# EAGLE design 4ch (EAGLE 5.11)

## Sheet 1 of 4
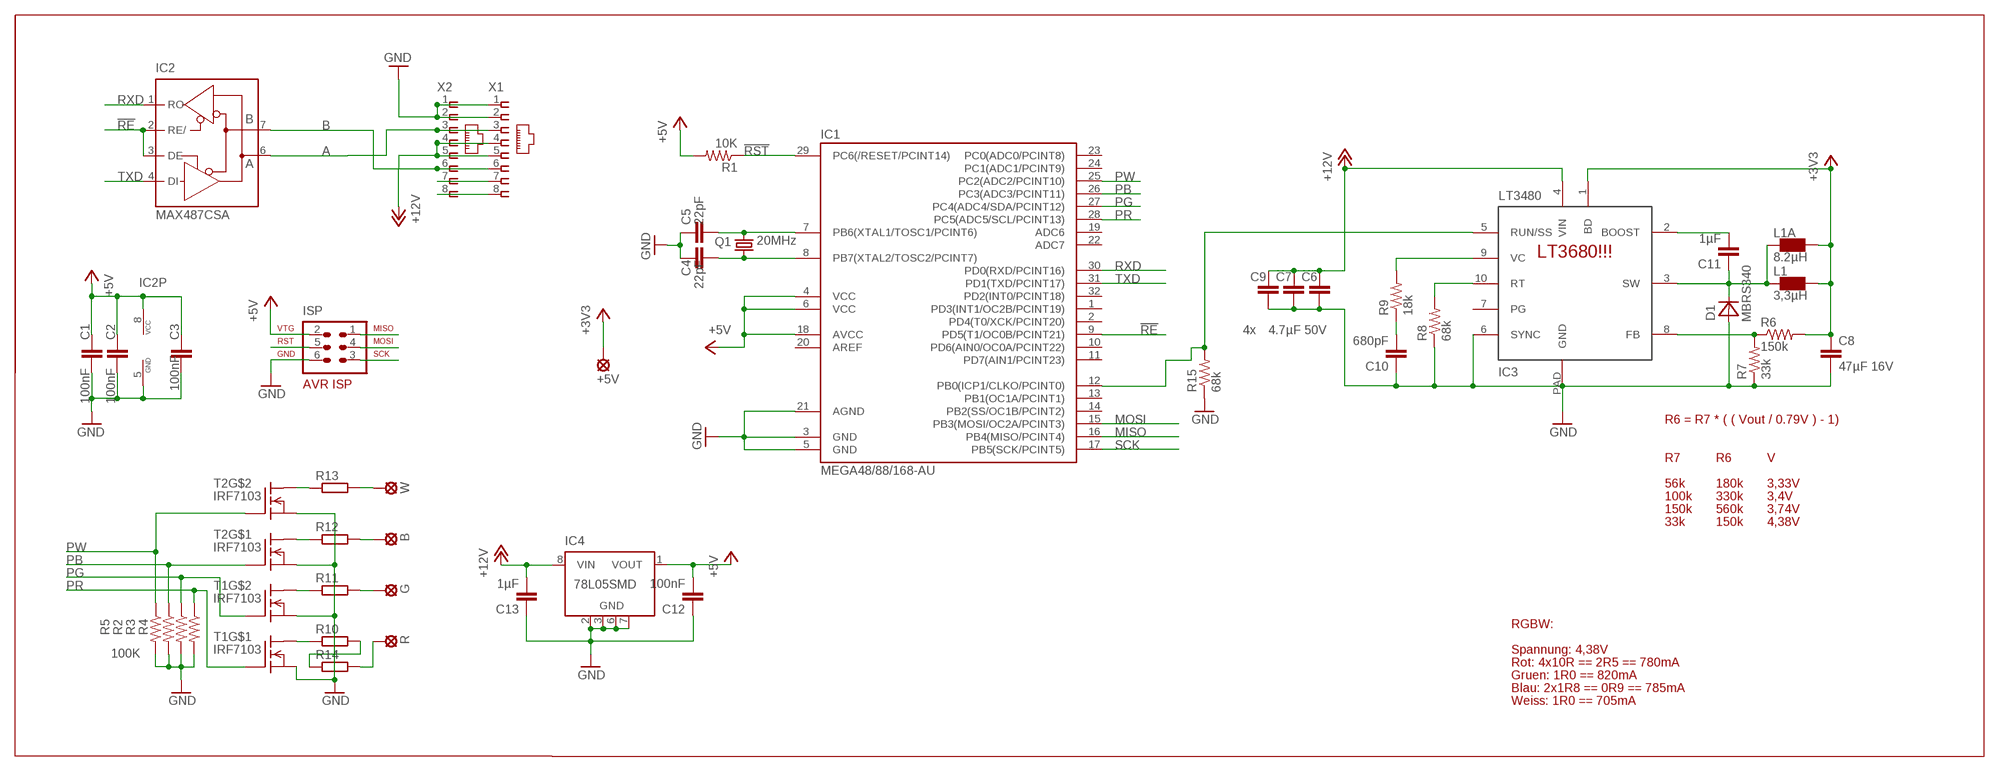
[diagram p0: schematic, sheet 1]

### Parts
+5V  SE14  [SE14]
B  SE14  [SE14]
C1  100nF  CAP0402-CAP  [0402-CAP]
C2  100nF  CAP0402-CAP  [0402-CAP]
C3  100nF  CAP0402-CAP  [0402-CAP]
C4  22pF  CAP0402-CAP  [0402-CAP]
C5  22pF  CAP0402-CAP  [0402-CAP]
C6  4.7µF 50V  CAP1210  [1210]
C7  4.7µF 50V  CAP1210  [1210]
C8  47µF 16V  CAP1210  [1210]
C9  4.7µF 50V  CAP1210  [1210]
C10  680pF  CAP0805  [0805]
C11  1µF  CAP0805  [0805]
C12  100nF  CAP0402-CAP  [0402-CAP]
C13  1µF  CAP0805  [0805]
D1  MBRS340  [DO214AB]
G  SE14  [SE14]
IC1  MEGA48/88/168-AU  [TQFP32-08]
IC2  MAX487CSA  MAX481CSA  [SO08]
IC3  LT3972  LT3480  [MSOP10-PAD]
IC4  78L05SMD  [SO08]
ISP  AVR-ISP-6  [AVR-ISP-6]
L1  3,3µH  TDK_RLF7030  [RLF7030]
L1A  8.2µH  IHLP-2525CZ  [IHLP-2525CZ]
Q1  20MHz  X22-OSCILLATOR  [X22]
R  SE14  [SE14]
R1  10K  RESISTOR0402-RES  [0402-RES]
R2  100K  RESISTOR0402-RES  [0402-RES]
R3  100K  RESISTOR0402-RES  [0402-RES]
R4  100K  RESISTOR0402-RES  [0402-RES]
R5  100K  RESISTOR0402-RES  [0402-RES]
R6  150k  RESISTOR0805-RES  [0805]
R7  33k  RESISTOR0805-RES  [0805]
R8  68k  RESISTOR0805-RES  [0805]
R9  18k  RESISTOR0805-RES  [0805]
R10  R-EU_MELF0207R  [MINI_MELF-0207R]
R11  R-EU_MELF0207R  [MINI_MELF-0207R]
R12  R-EU_MELF0207R  [MINI_MELF-0207R]
R13  R-EU_MELF0207R  [MINI_MELF-0207R]
R14  R-EU_MELF0207R  [MINI_MELF-0207R]
R15  68k  RESISTOR0402-RES  [0402-RES]
T1  IRF7103  [SO-8]
T2  IRF7103  [SO-8]
W  SE14  [SE14]
X1  RJ45-8L-B  [RJ45-NO-SHIELD]
X2  RJ45-8L-B  [RJ45-NO-SHIELD]

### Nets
!RE: IC1.9(PD5(T1/OC0B/PCINT21)) IC2.2(RE/) IC2.3(DE)
!RST: IC1.29(PC6(/RESET/PCINT14)) ISP.5 R1.1
+3V3: +5V.MP C8.1 IC3.1(BD) L1.P$1 L1A.P$1 R6.2
+5V: C1.1 C2.1 C3.1 C12.2 IC1.4(VCC) IC1.6(VCC) IC1.18(AVCC) IC2.8(VCC) IC4.1(VOUT) ISP.2 R1.2
+12V: C6.1 C7.1 C9.1 C13.2 IC3.4(VIN) IC4.8(VIN) X1.4 X1.5 X2.4 X2.5
A: IC2.6(A) X1.3 X2.3
B: IC2.7(B) X1.6 X2.6
GND: C1.2 C2.2 C3.2 C4.1 C5.1 C6.2 C7.2 C8.2 C9.2 C10.1 C12.1 C13.1 D1.A IC1.3(GND) IC1.5(GND) IC1.21(AGND) IC2.5(GND) IC3.6(SYNC) IC3.PAD(GND) IC4.2(GND) IC4.3(GND) IC4.6(GND) IC4.7(GND) ISP.6 R2.2 R3.2 R4.2 R5.2 R7.1 R8.1 R15.1 T1.1(S) T1.3(S) T2.1(S) T2.3(S) X1.1 X1.2 X2.1 X2.2
MISO: IC1.16(PB4(MISO/PCINT4)) ISP.1
MOSI: IC1.15(PB3(MOSI/OC2A/PCINT3)) ISP.4
N$1: R10.1 T1.8(D1)
N$2: R13.2 W.MP
N$3: R13.1 T2.5(D1)
N$4: R11.1 T1.5(D1)
N$5: R12.1 T2.8(D1)
N$6: IC3.10(RT) R8.2
N$8: G.MP R11.2
N$9: B.MP R12.2
N$10: C10.2 R9.1
N$11: R10.2 R14.1
N$12: IC1.12(PB0(ICP1/CLKO/PCINT0)) IC3.5(RUN/SS) R15.2
N$13: R14.2 R.MP
N$14: IC3.9(VC) R9.2
N$15: C11.1 D1.K(C) IC3.3(SW) L1.P$2 L1A.P$2
N$16: IC3.8(FB) R6.1 R7.2
N$17: C11.2 IC3.2(BOOST)
N$18: X1.7 X2.7
N$19: X1.8 X2.8
PB: IC1.26(PC3(ADC3/PCINT11)) R2.1 T2.2(G)
PG: IC1.27(PC4(ADC4/SDA/PCINT12)) R3.1 T1.4(G)
PR: IC1.28(PC5(ADC5/SCL/PCINT13)) R4.1 T1.2(G)
PW: IC1.25(PC2(ADC2/PCINT10)) R5.1 T2.4(G)
RXD: IC1.30(PD0(RXD/PCINT16)) IC2.1(RO)
SCK: IC1.17(PB5(SCK/PCINT5)) ISP.3
TXD: IC1.31(PD1(TXD/PCINT17)) IC2.4(DI)
XTAL1: C5.2 IC1.7(PB6(XTAL1/TOSC1/PCINT6)) Q1.3
XTAL2: C4.2 IC1.8(PB7(XTAL2/TOSC2/PCINT7)) Q1.1
Unconnected: IC1.1(PD3(INT1/OC2B/PCINT19)) IC1.2(PD4(T0/XCK/PCINT20)) IC1.10(PD6(AIN0/OC0A/PCINT22)) IC1.11(PD7(AIN1/PCINT23)) IC1.13(PB1(OC1A/PCINT1)) IC1.14(PB2(SS/OC1B/PCINT2)) IC1.19(ADC6) IC1.20(AREF) IC1.22(ADC7) IC1.23(PC0(ADC0/PCINT8)) IC1.24(PC1(ADC1/PCINT9)) IC1.32(PD2(INT0/PCINT18)) IC3.7(PG) IC4.4(NC) IC4.5(NC) T1.6(D) T1.7(D) T2.6(D) T2.7(D)

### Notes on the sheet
- LT3680!!!
- 4x
- R6 = R7 * ( ( Vout / 0.79V ) - 1)
- R7 | R6 | V
- 56k | 180k | 3,33V
- 100k | 330k | 3,4V
- 150k | 560k | 3,74V
- 33k | 150k | 4,38V
- RGBW:
- Spannung: 4,38V
- Rot: 4x10R == 2R5 == 780mA
- Gruen: 1R0 == 820mA
- Blau: 2x1R8 == 0R9 == 785mA
- Weiss: 1R0 == 705mA

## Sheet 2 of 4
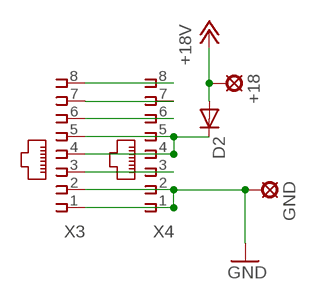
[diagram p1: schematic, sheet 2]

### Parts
+18  SE14  [SE14]
D2  DIODE-TO220V  [TO220ACS]
GND  SE14  [SE14]
X3  RJ45-8L-B  [RJ45-NO-SHIELD]
X4  RJ45-8L-B  [RJ45-NO-SHIELD]

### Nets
+18V: +18.MP D2.A
+18V_PI: D2.C X3.4 X3.5 X4.4 X4.5
A_PI: X3.3 X4.3
B_PI: X3.6 X4.6
GND_PI: GND.MP X3.1 X3.2 X4.1 X4.2 ; supply symbol labelled GND
N$20: X3.7 X4.7
N$21: X3.8 X4.8

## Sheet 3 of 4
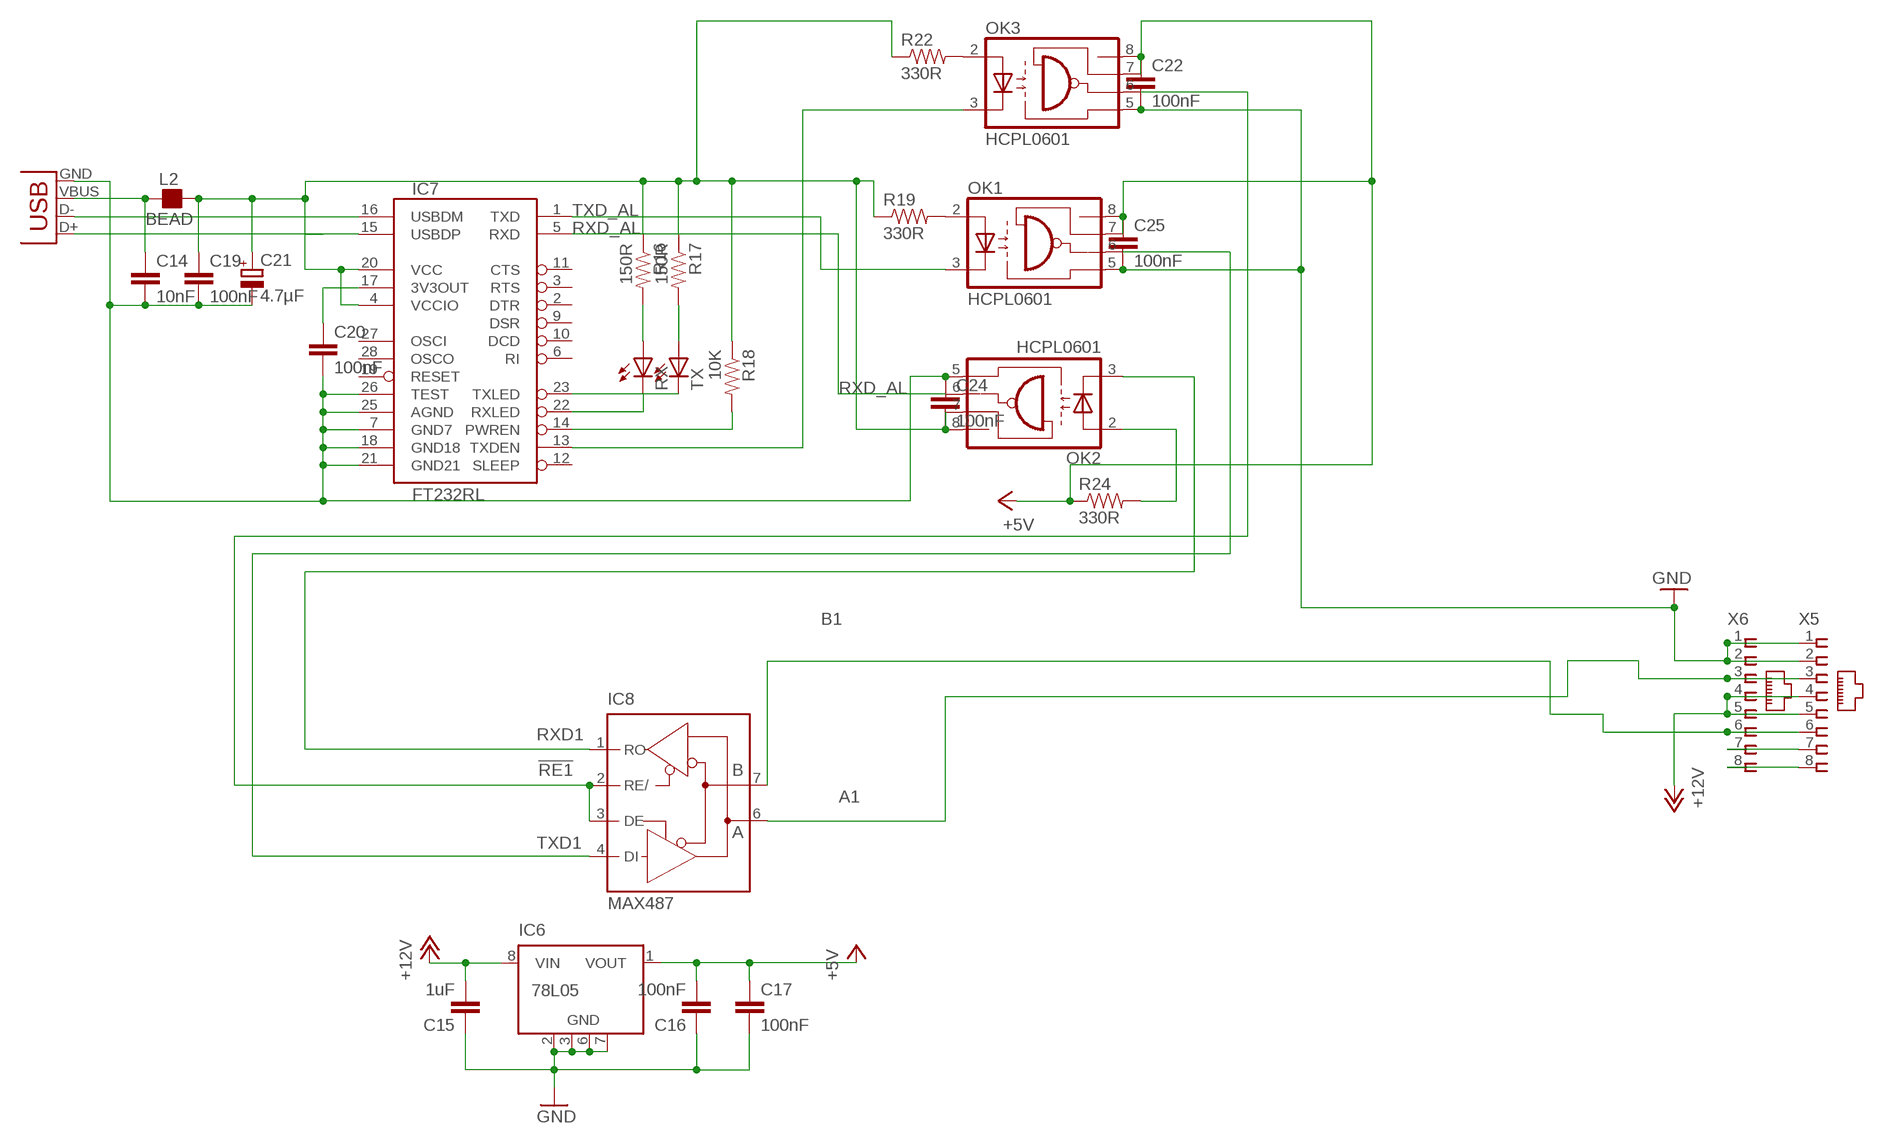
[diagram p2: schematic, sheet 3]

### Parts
C14  10nF  CAP0805  [0805]
C15  1uF  CAP0805  [0805]
C16  100nF  CAP0805  [0805]
C17  100nF  CAP0805  [0805]
C19  100nF  CAP0805  [0805]
C20  100nF  CAP0805  [0805]
C21  4.7µF  CPOL-EUSMCC  [SMC_C]
C22  100nF  CAP0805  [0805]
C24  100nF  CAP0805  [0805]
C25  100nF  CAP0805  [0805]
IC6  78L05  78L05SMD  [SO08]
IC7  FT232RL  FT232RLSSOP  [SSOP28DB]
IC8  MAX487  MAX481CSA  [SO08]
L2  BEAD  FB_0805  [L0805]
OK1  HCPL0601  [SOIC08]
OK2  HCPL0601  [SOIC08]
OK3  HCPL0601  [SOIC08]
R16  150R  RESISTOR0805-RES  [0805]
R17  150R  RESISTOR0805-RES  [0805]
R18  10K  RESISTOR0805-RES  [0805]
R19  330R  RESISTOR0805-RES  [0805]
R22  330R  RESISTOR0805-RES  [0805]
R24  330R  RESISTOR0805-RES  [0805]
RX  LEDCHIP-LED0805  [CHIP-LED0805]
TX  LEDCHIP-LED0805  [CHIP-LED0805]
X5  RJ45-8L-B  [RJ45-NO-SHIELD]
X6  RJ45-8L-B  [RJ45-NO-SHIELD]
X7  USB-SMD-NS  [USB-MINIB-NOSTOP]

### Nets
!RE1: IC8.2(RE/) IC8.3(DE) OK3.6(VO)
+5V1: C16.2 C17.1 C22.1 C25.1 IC6.1(VOUT) OK1.7(VE) OK1.8(VCC) OK3.7(VE) OK3.8(VCC) R24.1 ; supply symbol labelled +5V
+24V: C15.2 IC6.8(VIN) X5.4 X5.5 X6.4 X6.5 ; supply symbol labelled +12V
+USB_SIEVED: C19.1 C21.+ C24.2 IC7.4(VCCIO) IC7.20(VCC) L2.2 OK2.7(VE) OK2.8(VCC) R16.1 R17.1 R18.1 R19.1 R22.1
A1: IC8.6(A) X5.3 X6.3
B1: IC8.7(B) X5.6 X6.6
GND_AL: C15.1 C16.1 C17.2 C22.2 C25.2 IC6.2(GND) IC6.3(GND) IC6.6(GND) IC6.7(GND) OK1.5(GND) OK3.5(GND) X5.1 X5.2 X6.1 X6.2 ; supply symbol labelled GND
GND_USB: C14.2 C19.2 C20.2 C21.- C24.1 IC7.7(GND7) IC7.18(GND18) IC7.21(GND21) IC7.25(AGND) IC7.26(TEST) OK2.5(GND) X7.GND
N$7: IC7.16(USBDM) X7.D-
N$22: X5.8 X6.8
N$23: X5.7 X6.7
N$24: IC7.15(USBDP) X7.D+
N$25: R16.2 RX.A
N$26: R17.2 TX.A
N$27: IC7.22(RXLED) RX.C
N$28: IC7.23(TXLED) TX.C
N$29: C20.1 IC7.17(3V3OUT)
N$30: C14.1 L2.1 X7.VBUS
N$31: IC7.14(PWREN) R18.2
N$32: OK1.2(A) R19.2
N$35: IC7.13(TXDEN) OK3.3(C)
N$37: OK2.2(A) R24.2
N$44: OK3.2(A) R22.2
RXD1: IC8.1(RO) OK2.3(C)
RXD_AL: IC7.5(RXD) OK2.6(VO)
TXD1: IC8.4(DI) OK1.6(VO)
TXD_AL: IC7.1(TXD) OK1.3(C)
Unconnected: IC6.4(NC) IC6.5(NC) IC7.2(DTR) IC7.3(RTS) IC7.6(RI) IC7.9(DSR) IC7.10(DCD) IC7.11(CTS) IC7.12(SLEEP) IC7.19(RESET) IC7.27(OSCI) IC7.28(OSCO)

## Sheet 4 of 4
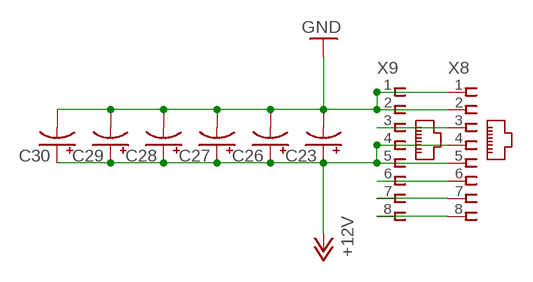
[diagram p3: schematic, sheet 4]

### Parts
C23  CAP_POLH13  [PANASONIC_H13]
C26  CAP_POLH13  [PANASONIC_H13]
C27  CAP_POLH13  [PANASONIC_H13]
C28  CAP_POLH13  [PANASONIC_H13]
C29  CAP_POLH13  [PANASONIC_H13]
C30  CAP_POLH13  [PANASONIC_H13]
X8  RJ45-8L-B  [RJ45-NO-SHIELD]
X9  RJ45-8L-B  [RJ45-NO-SHIELD]

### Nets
+24V_SB: C23.+ C26.+ C27.+ C28.+ C29.+ C30.+ X8.4 X8.5 X9.4 X9.5 ; supply symbol labelled +12V
A1_1: X8.3 X9.3
B1_1: X8.6 X9.6
GND_SB: C23.- C26.- C27.- C28.- C29.- C30.- X8.1 X8.2 X9.1 X9.2 ; supply symbol labelled GND
N$33: X8.8 X9.8
N$34: X8.7 X9.7

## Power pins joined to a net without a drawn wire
+5V1: IC8.8(VCC)
GND_AL: IC8.5(GND)

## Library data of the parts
+5V +18 B G GND R W = solpad:SE14: SOLDER PAD
C1-C17 C19 C20 C22 C24 C25 = SparkFun:CAP: Capacitor
C21 = resistor:CPOL-EU: POLARIZED CAPACITOR, European symbol
C23 C26-C30 = SparkFun:CAP_POL: Capacitor Polarized
D1 = seb:MBRS340
D2 = diode:DIODE-: DIODE
IC1 = avr-7:MEGA48/88/168
IC2 IC8 = maxim:MAX481CSA: RS485 TRANSEIVER; MF: MAXIM; MPN: MAX481CSA; OC_FARNELL: unknown; OC_NEWARK: 90C3817
IC3 = seb:LT3480
IC4 IC6 = linear:78L*SMD: Positive VOLTAGE REGULATOR
IC7 = SparkFun:FT232RL: USB UART FT232RL 4th Generation USB UART (USB <-> Serial) Controller. Spark Fun Electronics SKU : COM-00650
ISP = atmel:AVR-ISP-6: AVR ISP-6 Serial Programming Header
L1 = seb:TDK_RLF7030
L1A = seb:IHLP-2525CZ
L2 = rc-master-smd:FB_: FERRITE BEAD
OK1-OK3 = optocoupler:HCPL0601: HEWLETT PACKARD OPTO COUPLER; MF: AGILENT TECHNOLOGIES; MPN: HCPL-0601-000E; OC_FARNELL: 9995102; OC_NEWARK: 88H7776
Q1 = seb:X22-OSCILLATOR
R1-R9 R15-R19 R22 R24 = SparkFun:RESISTOR: Resistor
R10-R14 = rcl:R-EU_: RESISTOR, European symbol
RX TX = led:LED: LED
T1 T2 = transistor-fet+irf7201:IRF7103
X1-X6 X8 X9 = con-tycoelectronics:RJ45: CORCOM Modular RJ Jacks No Shield Source: www.tycoelectronics.com .. ENG_DS_1654001_1099_RJ_L_0507.pdf; MF: TYCO ELECTRONICS; MPN: RJ45-8L-B; OC_FARNELL: 1279843; OC_NEWARK: 52K4445
X7 = SparkFun:USB: USB Connectors USB-B-PTH is fully proven SKU : PRT-00139 USB-miniB is fully proven SKU : PRT-00587 USB-A-PCB is untested. USB-A-H is throughly reviewed, but untested. Spark Fun Electronics SKU : PRT-00437 USB-B-SMT is throughly reviewed, but untested. Needs silkscreen touching up. USB-A-S has not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

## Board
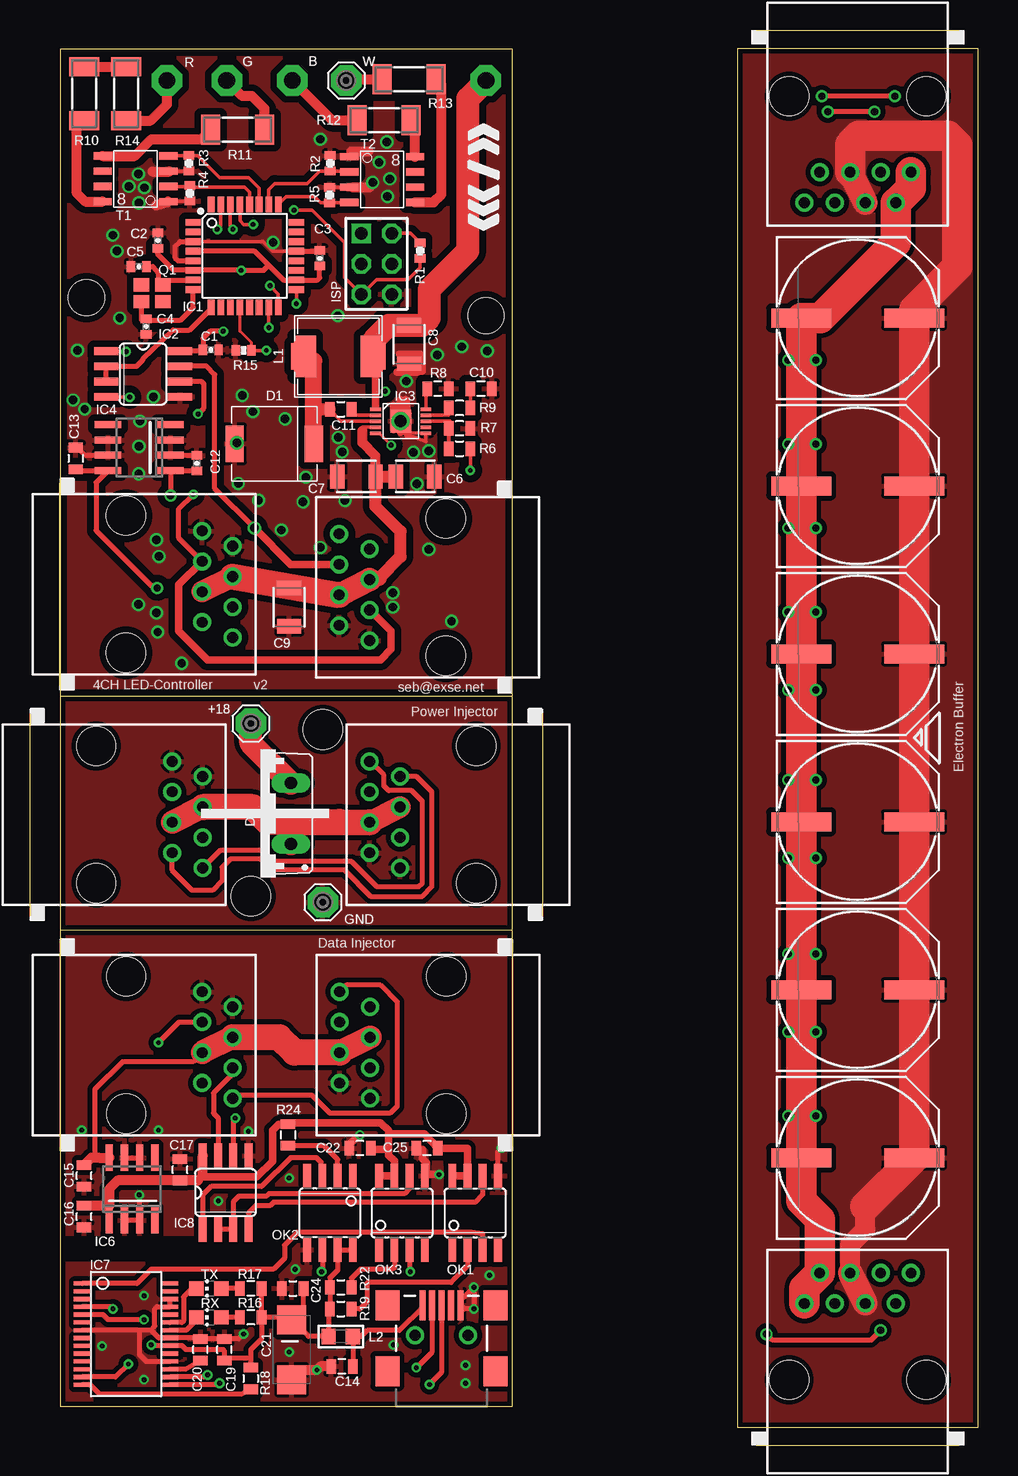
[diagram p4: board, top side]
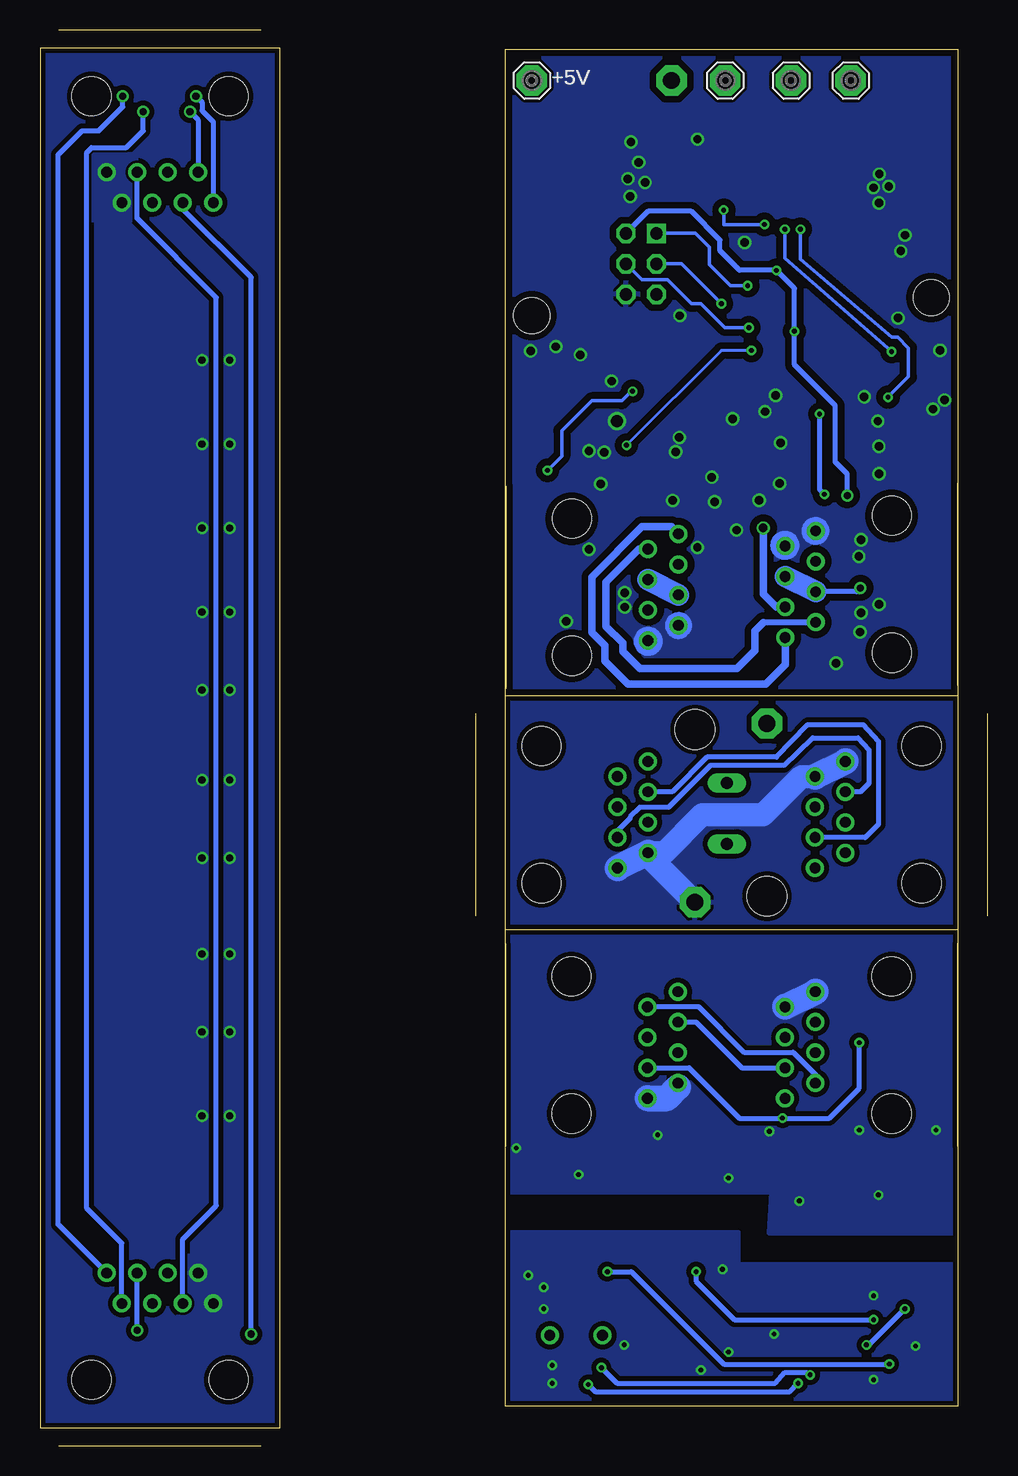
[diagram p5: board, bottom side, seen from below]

Size 79.01 x 118.02 mm. Coordinates in mm from the lower left corner, seen from the top.
Outline: 2.51,62.51 40.21,62.51
Outline: 40.21,62.51 40.21,116.41 2.51,116.41 2.51,62.51
Outline: 2.51,62.51 2.51,43.01
Outline: 2.51,43.01 40.21,43.01
Outline: 40.21,43.01 40.21,62.51
Outline: 2.51,43.01 2.51,3.31 40.21,3.31 40.21,43.01
Outline: 59.01,116.51 79.01,116.51 79.01,1.51 59.01,1.51 59.01,116.51
Copper layers (1*16): Top 0.035mm / dielectric 1.5mm / Bottom 0.035mm
Design rules "default *": minimum track width 0.2mm, minimum drill 0.4mm, track to track 0.2mm, track to pad 0.2mm, pad to pad 0.2mm, via to via 0.2mm, smd to smd 0mil, copper to edge 0.4mm, drill to drill 8mil, minimum pad ring 0.3mm, minimum via ring 8mil, stop-mask expansion 4mil, vias tented up to drill 40mil, thermal gap 10mil
Holes 3.3 mm at 18.41,45.81 24.41,59.71
Holes 3 mm at 38.01,94.21 4.71,95.71

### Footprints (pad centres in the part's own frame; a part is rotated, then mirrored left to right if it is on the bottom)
SE14 = drill 1.397 pad 2.54 octagon: MP 0,0
0402-CAP = smd 0.7 x 0.9: 1 -0.65,0; 2 0.65,0
1210 = smd 1.2 x 2: 1 -1.6,0; 2 1.6,0
0805 = smd 0.8 x 1.2: 1 -0.9,0; 2 0.9,0
SMC_C = smd 2.4 x 2.4: + -2.5,0; - 2.5,0
PANASONIC_H13 = smd 5 x 1.6: + 4.7,0; - -4.7,0
DO214AB = smd 1.52 x 3.07: A 3.305,0; K -3.305,0
TO220ACS = drill 1.016 long: A 2.54,-2.54; C -2.54,-2.54
TQFP32-08 = smd 1.27 x 0.559: 1 -4.293,2.8; 2 -4.293,2; 3 -4.293,1.2; 4 -4.293,0.4; 5 -4.293,-0.4; 6 -4.293,-1.2; 7 -4.293,-2; 8 -4.293,-2.8; 17 4.293,-2.8; 18 4.293,-2; 19 4.293,-1.2; 20 4.293,-0.4; 21 4.293,0.4; 22 4.293,1.2; 23 4.293,2; 24 4.293,2.8 | smd 0.559 x 1.27: 9 -2.8,-4.293; 10 -2,-4.293; 11 -1.2,-4.293; 12 -0.4,-4.293; 13 0.4,-4.293; 14 1.2,-4.293; 15 2,-4.293; 16 2.8,-4.293; 25 2.8,4.293; 26 2,4.293; 27 1.2,4.293; 28 0.4,4.293; 29 -0.4,4.293; 30 -1.2,4.293; 31 -2,4.293; 32 -2.8,4.293
SO08 = smd 0.66 x 2.032: 1 -1.905,-3.073; 2 -0.635,-3.073; 3 0.635,-3.073; 4 1.905,-3.073; 5 1.905,3.073; 6 0.635,3.073; 7 -0.635,3.073; 8 -1.905,3.073
MSOP10-PAD = smd 0.305 x 0.889: 1 -1,-2.095; 2 -0.5,-2.095; 3 0,-2.095; 4 0.5,-2.095; 5 1,-2.095; 6 1,2.095; 7 0.5,2.095; 8 0,2.095; 9 -0.5,2.095; 10 -1,2.095 | smd 1.88 x 1.68: PAD 0,0
SO08' = smd 0.6 x 2.2: 1 -1.905,-2.6; 2 -0.635,-2.6; 3 0.635,-2.6; 4 1.905,-2.6; 5 1.905,2.6; 6 0.635,2.6; 7 -0.635,2.6; 8 -1.905,2.6
SSOP28DB = smd 0.348 x 1.397: 1 -4.225,-3.656; 2 -3.575,-3.656; 3 -2.925,-3.656; 4 -2.275,-3.656; 5 -1.625,-3.656; 6 -0.975,-3.656; 7 -0.325,-3.656; 8 0.325,-3.656; 9 0.975,-3.656; 10 1.625,-3.656; 11 2.275,-3.656; 12 2.925,-3.656; 13 3.575,-3.656; 14 4.225,-3.656; 15 4.225,3.656; 16 3.575,3.656; 17 2.925,3.656; 18 2.275,3.656; 19 1.625,3.656; 20 0.975,3.656; 21 0.325,3.656; 22 -0.325,3.656; 23 -0.975,3.656; 24 -1.625,3.656; 25 -2.275,3.656; 26 -2.925,3.656; 27 -3.575,3.656; 28 -4.225,3.656
AVR-ISP-6 = drill 1.016 square: 1 -2.54,-1.27 | drill 1.016 octagon: 2 -2.54,1.27; 3 0,-1.27; 4 0,1.27; 5 2.54,-1.27; 6 2.54,1.27
RLF7030 = smd 2 x 2.2: P$1 -2.95,0; P$2 2.95,0
IHLP-2525CZ = smd 1.83 x 3.43: P$1 -2.77,0; P$2 2.77,0
L0805 = smd 1.2 x 1.3: 1 -1.016,0; 2 1.016,0
SOIC08 = smd 0.66 x 2.032: 1 -1.905,-3.073; 2 -0.635,-3.073; 3 0.635,-3.073; 4 1.905,-3.073; 5 1.905,3.073; 6 0.635,3.073; 7 -0.635,3.073; 8 -1.905,3.073
X22 = smd 1.3 x 1.1: 1 0.9,0.7; 2 -0.9,0.7; 3 -0.9,-0.7; 4 0.9,-0.7
0402-RES = smd 0.7 x 0.9: 1 -0.65,0; 2 0.65,0
MINI_MELF-0207R = smd 1.6 x 2.5: 1 -2.25,0; 2 2.25,0
CHIP-LED0805 = smd 1.2 x 1.2: A 0,-1.05; C 0,1.05
SO-8 = smd 1.524 x 0.61: 1 -2.743,1.27; 2 -2.743,0; 3 -2.743,-1.27; 4 -2.743,-2.54; 5 2.743,-2.54; 6 2.743,-1.27; 7 2.743,0; 8 2.743,1.27
RJ45-NO-SHIELD = drill 0.9 pad 1.4 round: 1 -4.445,6.35; 2 -3.175,8.89; 3 -1.905,6.35; 4 -0.635,8.89; 5 0.635,6.35; 6 1.905,8.89; 7 3.175,6.35; 8 4.445,8.89 | hole 3.251: -5.715,0; 5.715,0
USB-MINIB-NOSTOP = smd 2.5 x 0.5: D+ 2.5,0; D- 2.5,0.8; GND 2.5,-1.6; ID 2.5,-0.8; VBUS 2.5,1.6 | smd 2.5 x 2: G1 -3,-4.5; G2 -3,4.5; G3 2.5,4.5; G4 2.5,-4.5 | drill 0.9 pad 0.8 round: H1 0,2.2 | drill 0.9 pad 0.787 round: H2 0,-2.2

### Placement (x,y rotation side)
+5V  38.01,113.81 0 bottom
+18  18.41,60.21 0 top
B  21.88,113.81 0 bottom
C1  15.08,91.36 0 top
C2  10.67,100.47 90 top
C3  24.16,99 90 top
C4  9.69,93.3 90 top
C5  9.07,98.3 0 top
C6  32.11,80.81 0 top
C7  27.21,80.81 180 top
C8  31.61,91.81 270 top
C9  21.61,69.91 270 top
C10  37.61,88.11 180 top
C11  25.91,86.41 0 top
C12  13.91,81.91 270 top
C13  3.81,82.31 270 top
C14  26.01,6.61 180 top
C15  4.51,22.51 90 top
C16  4.51,19.11 90 top
C17  12.51,23.01 90 top
C19  16.21,8.01 90 top
C20  14.21,8.01 90 top
C21  21.81,8.01 270 top
C22  27.51,24.81 180 top
C23  69.01,94.01 0 top
C24  21.91,13.11 0 top
C25  33.11,24.81 180 top
C26  69.01,80.01 0 top
C27  69.01,66.01 0 top
C28  69.01,52.01 0 top
C29  69.01,38.01 0 top
C30  69.01,24.01 0 top
D1  20.36,83.52 180 top
D2  19.21,52.71 90 top
G  16.4,113.81 0 bottom
GND  24.41,45.31 0 top
IC1  17.91,99.19 0 top
IC2  9.43,89.35 270 top
IC3  30.91,85.41 270 top
IC4  78L05SMD  [SO08']  9.11,83.21 90 top
IC6  78L05  [SO08']  8.51,21.41 0 top
IC7  8.01,9.31 270 top
IC8  16.31,21.11 0 top
ISP  28.89,98.53 270 top
L1  25.71,90.81 180 top
L1A  25.71,90.81 180 top
L2  25.91,9.11 180 top
OK1  37.11,19.41 0 top
OK2  25.01,19.41 180 top
OK3  31.01,19.41 0 top
Q1  10.18,96.07 180 top
R  11.42,113.81 0 bottom
R1  32.53,99.63 90 top
R2  25.03,106.91 90 top
R3  13.25,106.91 270 top
R4  13.33,104.41 270 top
R5  24.98,104.26 90 top
R6  35.81,83.11 0 top
R7  35.81,84.81 180 top
R8  34.01,88.11 180 top
R9  35.81,86.51 180 top
R10  4.51,112.71 90 top
R11  17.31,109.71 0 top
R12  29.51,110.51 180 top
R13  31.61,113.91 180 top
R14  8.01,112.71 270 top
R15  17.81,91.31 0 top
R16  18.41,10.71 180 top
R17  18.41,13.11 180 top
R18  18.41,5.61 270 top
R19  25.91,11.41 0 top
R22  25.91,13.21 0 top
R24  21.51,25.91 270 top
RX  14.91,10.71 90 top
T1  8.8,104.98 180 top
T2  29.36,106.19 0 top
TX  14.91,13.11 90 top
W  26.37,113.81 0 top
X1  34.67,71.57 90 top
X2  8,71.83 270 top
X3  5.51,52.61 270 top
X4  37.21,52.61 90 top
X5  8.01,33.41 270 top
X6  34.71,33.41 90 top
X7  34.31,9.21 90 top
X8  69.01,5.51 0 top
X9  69.01,112.51 180 top

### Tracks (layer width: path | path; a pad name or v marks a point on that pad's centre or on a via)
!RE
  Top 0.406: IC1.9 15.11,94.81 13.31,93.01 11.91,93.01 9.41,90.61 9.41,90.51 8.88,89.98 IC2.2 IC2.3
!RE1
  Top 0.305: OK3.6 31.65,21.45
  Top 0.406: 31.65,21.45 31.21,21.01 19.91,21.01 19.71,20.81 17.41,20.81 16.95,20.35 IC8.3 IC8.2
!RST  (via drill 0.4)
  Top 0.305: IC1.29 17.51,102.12 17.81,101.81 v18.61,101.81 | v22.01,103.01 23.51,103.01 26.21,100.31 26.21,97.4 ISP.5 27.69,95.99 28.91,97.21 31.51,97.21 32.53,98.23 R1.1
  Bottom 0.305: v18.61,101.81 22.01,101.81 v22.01,103.01
+3V3  (via drill 0.4)
  Top 0.254: L1.P$1 L1A.P$1
  Top 0.305: IC3.1 28.81,87.31 | v36.71,81.31 R6.2 | 28.81,87.91 v29.61,87.91
  Top 0.61: 28.81,86.61 28.81,87.31 28.81,87.91 28.81,90.41 L1.P$1
  Top 1.93: L1.P$1 28.66,92.16 29.91,93.41 C8.1 32.71,93.41 33.31,94.01 33.31,96.41 36.51,99.61 36.51,112.31 +5V.MP
  Bottom 0.305: v36.71,81.31 35.51,82.51 35.51,84.61 33.01,87.11 30.51,87.11 29.71,87.91 v29.61,87.91
+5V  (via drill 0.4, 0.6)
  Top 0.305: R1.2 31.74,101.07 ISP.2
  Top 0.406: C2.1 10.65,99.89 10.65,99.33 11.99,97.99 IC1.6 v17.61,97.99 19.49,97.99 19.91,98.41 | 19.91,98.41 18.74,99.59 IC1.4 | 19.91,98.41 21.14,97.19 IC1.18 23.99,97.19 24.16,97.36 C3.1 | C12.2 13.81,81.31 IC4.1 v11.71,79.21 | IC2.8 14.37,91.25 C1.1 14.43,92.33 15.01,92.91 v16.11,92.91
  Bottom 0.406: ISP.2 28.32,102.91 24.71,102.91 22.31,100.51 22.31,99.61 20.69,97.99 v17.61,97.99 16.11,96.49 v16.11,92.91 16.11,90.11 12.71,86.71 12.71,82.01 11.71,81.01 v11.71,79.21
+5V1
  Top 0.406: 29.91,26.01 29.91,26.31 | 6.61,18.41 IC6.1 6.61,20.01 | 28.51,24.71 C22.1 | 36.48,24.8 36.46,24.81 | 14.41,22.51 14.31,22.41 14.01,22.11
  Top 0.61: OK1.8 OK1.7 36.48,24.8 | OK3.8 OK3.7 30.38,23.75 29.91,24.21 29.91,24.71 | 29.91,26.31 29.21,26.91 21.71,26.91 arc90 R24.1 20.71,26.81 20.21,26.31 20.21,23.71 18.91,22.41 14.31,22.41 | 29.91,24.71 29.91,26.01 32.91,26.01 C25.1 36.46,24.81 | 29.91,24.71 28.51,24.71
  Top 0.813: 14.41,22.51 IC8.8 | 14.01,22.11 C17.1 7.31,22.11 6.61,21.41 6.61,20.01 C16.2
+12V  (via drill 0.6)
  Top 0.3: IC3.4 27.71,84.91 27.71,84.61
  Top 0.406: v10.61,71.51 10.31,71.51 5.51,76.31 5.51,80.31 IC4.8 4.12,81.31 C13.2
  Top 0.813: 27.71,84.61 27.71,83.61 28.81,82.51 C7.1
  Top 1.016: 29.01,72.21 29.11,72.31 30.91,74.11 30.91,76.21 28.81,78.31 C7.1 C6.1 | C9.1 22.89,70.94 X1.4
  Top 1.27: X1.5 29.11,72.31
  Top 1.778: X2.5 X2.4
  Top 1.93: X1.5 25.81,70.91 X1.5
  Top 2.184: X2.4 X1.4
  Bottom 0.406: v10.61,71.51 10.93,71.19 X2.5
  Bottom 1.778: X1.4 X1.5 | X2.5 X2.4
+18V
  Top 1.93: D2.A 18.41,58.59 +18.MP
+18V_PI
  Top 1.8: X4.4 X4.5
  Top 1.93: X3.4 X3.5 | D2.C 21.75,51.95 21.81,52.01
  Top 2.184: X3.4 18.58,53.25 19.81,52.01 21.81,52.01 25.79,52.01 X4.4
+24V
  Top 0.406: 14.1,32.51 X5.5 13.6,32.01 7.71,32.01 5.41,29.71 5.41,24.31 5.71,24.01 | IC6.8 6.41,23.72
  Top 0.813: IC6.8 5.71,24.01 5.11,24.01 C15.2
  Top 1.93: X5.4 X5.5 | X6.5 X6.4
  Top 2.184: X6.4 22.05,32.78 20.78,34.05 X5.4
+24V_SB
  Top 1.676: X8.4 68.38,16.78 69.65,18.05 69.65,19.95
  Top 2.05: X8.5 X8.4 | X9.5 X9.4
  Top 2.54: X9.5 68.38,108.48 69.11,109.21 76.51,109.21 77.31,108.41 77.31,98.31 73.71,94.71 C23.+ C26.+ C27.+ C28.+ C29.+ C30.+ 69.65,19.95
  pour Top (isolate 0.406): 58.81,116.71 79.31,116.71 79.31,1.21 58.81,1.21
+USB_SIEVED  (via drill 0.4)
  Top 0.406: v10.11,8.41 10.19,8.34 IC7.20 12.69,8.34 13.01,8.01 16.11,8.01 16.21,7.91 C19.1 16.41,7.31 18.41,7.31 | v6.91,11.41 6.74,11.59 IC7.4 | 18.51,6.61 R18.1 18.41,7.31 | OK2.8 OK2.7 25.65,14.65 25.01,14.01 R22.1 R19.1 24.9,11.41 L2.2 23.21,9.11 C21.+ | C24.2 22.81,11.51 C21.+ | R16.1 21.61,10.71 C21.+ | R16.1 R17.1 | 18.41,7.31 18.41,8.01 19.31,8.91 R16.1
  Bottom 0.406: v10.11,8.41 9.91,8.41 v6.91,11.41
A  (via drill 0.4)
  Top 0.406: IC2.6 14.31,88.71 14.51,88.51 14.51,86.51 v14.01,86.01 | X2.3 12.41,75.67 12.41,78.11 v13.61,79.31
  Top 0.61: X1.3 28.36,69.67 30.11,67.91 30.11,66.41 29.21,65.51 14.81,65.51 12.41,67.91 12.41,71.79 X2.3
  Bottom 0.406: v14.01,86.01 14.01,79.71 v13.61,79.31
A1  (via drill 0.4)
  Top 0.406: v17.11,27.31 16.95,27.15 IC8.6 | v10.71,33.61 12.42,35.32 X5.3
  Bottom 0.406: X6.3 24.91,31.51 20.71,27.31 v17.11,27.31 13.21,27.31 10.71,29.81 v10.71,33.61
A1_1
  Bottom 0.406: X9.3 70.92,102.32 64.31,95.71 64.31,20.01 67.11,17.22 X8.3
A_PI
  Bottom 0.406: X4.3 30.86,51.26 29.81,52.31 29.81,52.41 29.01,53.21 26.61,53.21 23.11,56.71 17.01,56.71 14.61,59.01 10.81,59.01 9.91,58.01 9.91,55.21 10.61,54.52 X3.3
B  (via drill 0.7)
  Top 0.406: IC2.7 14.74,89.98 15.41,89.31 15.41,79.81 v18.71,76.51
  Top 0.61: X1.6 21.75,73.48 v18.71,76.51
  Bottom 0.61: v18.71,76.51 18.71,71.01 17.62,69.92 X2.6
B1
  Top 0.406: X5.6 16.9,31 15.31,29.41 15.31,27.71 15.68,27.35 IC8.7
  Bottom 0.406: X5.6 20.51,31.51 24.32,35.32 X6.6
B1_1  (via drill 0.6)
  Top 0.406: v61.41,9.31 61.91,8.81 70.11,8.81 v70.92,9.62
  Bottom 0.406: v61.41,9.31 61.41,97.41 67.11,103.11 X9.6 | v70.92,9.62 X8.6
B_PI
  Bottom 0.406: X3.6 10.22,50.71 9.11,51.81 9.11,58.71 10.41,60.11 15.01,60.11 17.61,57.41 23.41,57.41 26.31,54.52 X4.6
GND  (via drill 0.7, 1)
  Top 0.254: 31.72,84.41 IC3.6 33.01,83.71
  Top 0.305: R5.2 T2.3 | T1.3 11.56,106.26 R3.2 | IC1.21 20.24,99.59 19.41,100.41 19.39,100.39 IC1.3 | T1.1 11.7,103.76 R4.2 | 30.91,84.51 33.01,83.71
  Top 0.406: IC1.5 12.34,98.79 12.06,99.06 12.06,99.95 12.5,100.39 IC1.3 | C13.1 4.65,82.58 IC4.7 | IC4.2 13.98,82.58 C12.1 | C3.2 24.1,99.59 IC1.21 | 30.31,86.71 30.51,86.71 30.91,87.11 | 32.51,91.01 32.81,90.71 32.81,89.51 32.31,89.51 C8.2
  Top 0.61: 31.31,87.21 31.51,86.01 31.51,84.21 | 30.91,84.51 IC3.PAD 30.91,87.11 30.91,87.21 | 30.31,86.71 30.31,84.71 | 32.31,89.51 30.61,89.51 | 32.51,91.01 30.81,91.01
  Top 0.813: 26.81,107.91 28.21,107.91 | 28.51,105.21 28.31,105.01 28.31,104.91 26.91,104.91 | 10.21,106.21 11.61,106.21 | 10.51,103.41 11.51,103.71
  Bottom 0.61: 13.51,76.21 arc353 13.51,76.31 14.31,76.31 X2.1 | 16.01,75.11 arc-354 16.01,75.01 | 27.41,67.11 arc-354 27.41,67.01 | X1.2 25.4,68.01 25.31,67.71 arc340 25.11,67.91
  other vias: 24.21,108.92 29.75,108.69 29.81,104.16 29.1,107 30,105.62 28.57,105.31 25.67,94.21 33.96,90.95 20.27,100.31 38.12,91.27 36.01,91.63 8.25,104.99 9.04,106.01 9.53,104.87 9.07,103.61 31.36,88.75 6.9,100.92 7.25,99.59 32.26,80.2 31.97,82.82 7.48,94.01 33.25,82.95 3.97,91.31 3.6,87.17 30.89,85.43 4.56,86.42 10.3,87.45 9.16,85.42 9.07,83.31 21.26,85.62 17.7,87.56 9.06,81.02 25.71,84.05 18.57,86.21 17.26,83.62 26.26,78.8 26.03,82.85 17.36,80.22 23,80.75 30.26,71.12 30.26,69.92 22.76,78.7 19.06,78.82 20.95,76.33 24.2,74.89 10.55,69.43 9.05,70.13 10.75,74.13 10.55,75.53 12.65,65.23 10.65,67.83 33.25,74.73 35.15,68.73
  pour Bottom (isolate 0.559, rank 2): 0.65,116.29 0.21,62.51 41.1,62.51 41.19,116.19
  pour Top (isolate 0.559, rank 2): 0.53,116.37 0.31,62.51 41.33,62.51 41.19,116.29
GND_AL  (via drill 0.4)
  Top 0.406: v9.11,20.91 9.11,18.85 IC6.3 IC6.2 | IC6.7 IC6.6 | v4.31,26.31 4.41,26.21 | 26.61,25.11 C22.2 | OK3.5 33.04,22.61 | 32.71,24.71 C25.2 | OK1.5 39.02,24.52 v39.31,24.81
  Top 0.61: v27.51,25.91 26.61,25.11 | v34.11,22.61 33.04,22.61 33.04,23.58 32.71,23.91 32.71,24.71
  Bottom 2.184: X5.2 X5.1 | X6.1 26.76,28.97 25.81,29.91
  other vias: 10.71,26.31 18.21,26.21 21.61,22.31 15.71,20.41
  pour Bottom (isolate 0.406): 41.01,42.91 1.61,42.91 1.61,17.71 18.21,17.71 18.01,21.11 41.01,21.11
  pour Top (isolate 0.406): 41.01,42.91 1.61,42.91 1.61,17.71 18.81,17.71 18.81,17.41 19.51,17.41 19.51,21.11 41.01,21.11
GND_PI
  Bottom 1.93: GND.MP 28.32,49.22 X4.2 26.99,49.44 23.81,52.61 20.01,52.61 19.61,52.61 18.71,52.61 15.54,55.79 X3.2
  Bottom 2.184: X3.2 X3.1 | X4.2 X4.1
  pour Bottom (isolate 0.406): 0.11,62.41 0.11,43.51 42.71,43.51 42.71,62.41
  pour Top (isolate 0.406): 0.11,62.41 0.11,43.51 42.71,43.51 42.71,62.41
GND_SB  (via drill 0.6)
  Top 0.406: v65.51,63.01 64.31,64.21 64.31,64.11 v63.21,63.01
  Top 1.676: X8.2 65.81,14.43
  Top 2.54: C23.- C26.- | C23.- C27.- 64.31,64.21 C28.- C29.- C30.- 64.31,20.41 65.84,18.89 X8.2 64.57,13.13 X8.1 | C23.- 65.91,94.01 72.19,100.29 X9.2 | X9.1 73.46,104.86 72.21,103.61
  other vias: 65.51,90.51 65.51,83.51 65.51,76.51 65.51,69.51 65.51,55.51 65.51,49.01 65.51,41.01 65.51,34.51 65.51,27.51 63.21,90.51 63.21,83.51 63.21,76.51 63.21,69.51 63.21,55.51 63.21,49.01 63.21,41.01 63.21,34.51 63.21,27.51
  pour Bottom (isolate 0.406): 58.81,116.71 79.31,116.71 79.31,1.21 58.81,1.21
  pour Bottom (no thermals): 62.91,15.81 67.51,15.81 67.51,9.51 62.91,9.51
  pour Bottom (no thermals): 74.81,107.61 74.81,102.21 71.01,102.21 71.01,107.61
GND_USB  (via drill 0.4)
  Top 0.406: OK2.5 22.93,16.41 | X7.GND 36.21,11.41 v37.01,11.41 v37.01,13.21 36.21,12.41 35.91,12.41 36.01,12.51 | IC7.21 11.64,9.01 10.81,9.01 | 10.09,9.64 9.11,9.64 | 9.11,9.64 IC7.7 | 10.09,9.64 10.74,8.99 IC7.21 | IC7.18 9.69,7.04 9.11,7.61 9.11,9.64 | IC7.21 14.14,8.99 C20.2 C19.2 17.41,8.91 v17.81,9.31 | IC7.26 IC7.25 10.59,11.59 10.41,11.41 10.41,9.96 10.09,9.64
  Top 0.813: C14.2 24.21,6.61 v23.91,6.31 22.61,6.31 C21.-
  other vias: 22.11,14.71 21.61,7.81 36.31,6.71 9.51,12.51 6.01,8.31 9.51,5.51 38.31,14.21 30.31,8.41 36.31,5.21
  pour Bottom (isolate 0.406): 2.11,3.31 40.71,3.31 40.71,17.81 20.81,17.81 20.81,16.81 20.81,15.11 15.81,15.11 2.11,15.11
  pour Top (isolate 0.406): 2.11,3.31 40.71,3.31 40.71,17.81 20.81,17.81 20.81,16.81 20.81,15.11 15.81,15.11 2.11,15.11
MISO  (via drill 0.4)
  Top 0.305: v20.01,96.71 20.71,96.02 IC1.16
  Bottom 0.305: v20.01,96.71 21.46,96.71 23.21,98.46 23.21,99.91 24.37,101.07 ISP.1
MOSI  (via drill 0.4)
  Top 0.305: v19.91,93.21 19.91,94.02 IC1.15
  Bottom 0.305: ISP.4 28.85,97.21 26.71,97.21 24.71,95.21 23.91,95.21 21.91,93.21 v19.91,93.21
N$1
  Top 0.813: T1.8 4.61,103.71 3.91,104.41 3.91,109.86 R10.1
N$2
  Top 0.813: R13.2 26.47,113.91 W.MP
N$3
  Top 0.813: T2.5 33.65,103.65 34.31,104.31 34.31,113.46 R13.1
N$4
  Top 0.813: T1.5 8.72,107.52 10.11,108.91 14.26,108.91 R11.1
N$5
  Top 0.813: T2.8 32.1,110.17 R12.1
N$6
  Top 0.305: IC3.10 33.01,87.51 R8.2
N$7  (via drill 0.4)
  Top 0.406: IC7.16 14.49,5.74 v14.81,5.91 | v32.21,6.51 33.51,7.81 X7.D-
  Bottom 0.406: v14.81,5.91 15.11,6.11 16.91,6.11 17.71,5.21 30.91,5.21 v32.21,6.51
N$8
  Top 0.813: R11.2 19.56,111.46 18.51,112.51 17.7,112.51 G.MP
N$9
  Top 0.813: R12.2 25.18,110.51 B.MP
N$10
  Top 0.305: R9.1 C10.2
N$11
  Top 0.813: R10.2 R14.1
N$12  (via drill 0.4)
  Top 0.254: IC3.5 29.12,84.41 v30.11,83.41 | IC1.12 17.51,92.92 18.46,91.96 R15.2
  Top 0.3: R15.2 v19.71,91.31
  Bottom 0.254: v30.11,83.41 22.21,91.31 v19.71,91.31
N$13
  Top 0.813: R14.2 10.06,110.46 11.42,111.82 R.MP
N$14
  Top 0.305: IC3.9 34.91,85.91 R9.2
N$15
  Top 0.254: L1.P$2 L1A.P$2
  Top 0.305: IC3.3 25.91,85.41 C11.1
  Top 0.61: D1.K 23.66,86.41
  Top 1.016: 23.66,86.41 C11.1
  Top 1.422: D1.K 23.66,90.43 L1.P$2
N$16
  Top 0.3: R6.1 R7.2
  Top 0.305: IC3.8 35.01,85.41 R6.1
N$17
  Top 0.305: IC3.2 26.81,85.91 C11.2
N$18
  Bottom 0.5: 14.39,68.61 18.71,68.61
  Bottom 0.61: X1.7 29.08,74.75 31.81,72.01 31.81,68.31 30.41,66.91 30.41,66.21 29.01,64.81 20.91,64.81 19.41,66.31 19.41,67.91 18.71,68.61 | X2.7 14.39,68.61
N$19
  Bottom 0.61: X1.8 26.38,76.61 28.81,76.61 33.01,72.41 33.01,67.81 31.91,66.71 31.91,65.41 30.01,63.51 18.51,63.51 16.89,65.13 X2.8
N$20
  Top 0.406: X3.7 11.86,47.96 13.51,46.31 15.21,46.31 16.01,47.11 16.01,48.21 16.71,48.91 19.21,48.91 20.11,48.01 26.21,48.01 28.41,45.81 32.71,45.81 33.51,46.61 33.51,54.51 32.24,55.79 X4.7
N$21
  Top 0.406: X4.8 28.37,57.06 29.51,55.91 29.51,55.01 29.91,54.61 31.81,54.61 32.71,53.71 32.71,46.91 32.41,46.61 28.91,46.61 26.81,48.71 20.31,48.71 19.41,49.61 15.85,49.61 X3.8
N$22
  Top 0.406: X5.8 17.15,29.21 23.51,29.21 25.01,27.71 30.01,27.71 30.61,28.31 30.61,37.01 29.21,38.41 26.38,38.41 X6.8
N$23
  Bottom 0.406: X6.7 28.34,36.61 24.11,36.61 20.31,32.81 16.21,32.81 14.36,30.96 X5.7
N$24  (via drill 0.4)
  Top 0.406: v33.31,5.11 34.31,6.11 X7.D+ | IC7.15 15.69,5.09 arc90 v15.81,5.21
  Bottom 0.406: v15.81,5.21 16.51,4.51 32.71,4.51 v33.31,5.11
N$25
  Top 0.406: R16.2 RX.A
N$26
  Top 0.406: R17.2 TX.A
N$27
  Top 0.406: IC7.22 13.04,9.64 13.86,10.46 RX.C
N$28
  Top 0.406: IC7.23 12.69,10.29 12.81,10.41 12.81,12.41 13.51,13.11 TX.C
N$29
  Top 0.406: IC7.17 12.99,6.39 C20.1
N$30
  Top 0.406: X7.VBUS 32.71,11.51 30.81,9.61 28.11,9.61 27.61,9.11 L2.1 26.93,6.61 C14.1
N$31
  Top 0.406: R18.2 17.61,4.31 5.81,4.31 5.04,5.09 IC7.14
N$32
  Top 0.406: OK1.2 36.48,14.98 35.11,13.61 28.11,13.61 28.11,12.01 27.51,11.41 R19.2
N$33  (via drill 0.6)
  Top 0.406: v72.11,112.51 v66.01,112.51
  Bottom 0.406: X8.8 77.51,18.46 77.51,107.61 75.51,109.61 74.11,109.61 72.11,111.61 v72.11,112.51 | X9.8 64.57,110.37 65.51,111.31 65.51,112.01 v66.01,112.51
N$34  (via drill 0.6)
  Top 0.406: v70.41,111.21 v66.51,111.21
  Bottom 0.406: X8.7 72.19,16.89 75.11,19.81 75.11,107.81 74.71,108.21 71.81,108.21 70.41,109.61 v70.41,111.21 | X9.7 65.84,110.54 v66.51,111.21
N$35  (via drill 0.4)
  Top 0.406: OK3.3 31.65,14.58 v31.71,14.51 | v8.21,6.81 7.14,5.74 IC7.13
  Bottom 0.406: v31.71,14.51 29.71,14.51 22.01,6.81 v8.21,6.81
N$37
  Top 0.406: OK2.2 25.65,23.88 24.51,25.01 R24.2
N$44
  Top 0.406: OK3.2 30.38,14.88 30.21,14.71 27.56,14.71 26.81,13.96 R22.2
PB
  Top 0.305: T2.2 26.54,106.26 R2.1 24.16,106.26 23.11,105.21 20.41,105.21 19.91,104.71 IC1.26
PG
  Top 0.305: IC1.27 19.11,104.82 18.21,105.71 15.81,105.71 13.96,107.56 R3.1 11.59,107.56 T1.4
PR
  Top 0.305: IC1.28 18.31,104.52 17.91,104.91 13.47,104.91 R4.1 13.25,104.98 T1.2
PW
  Top 0.305: T2.4 26.58,103.61 R5.1 24.21,103.61 23.71,104.11 21.34,104.11 IC1.25
RXD  (via drill 0.4)
  Top 0.305: IC1.30 16.71,101.62 v16.91,101.41 | v8.01,91.21 6.4,91.21 IC2.1
  Bottom 0.305: v16.91,101.41 16.91,99.01 v8.01,91.21
RXD1
  Top 0.406: OK2.3 24.28,23.65 23.91,24.01 21.71,24.01 19.31,21.61 15.11,21.61 14.41,20.91 IC8.1
RXD_AL  (via drill 0.4)
  Top 0.406: OK2.6 24.38,14.58 v24.31,14.51 | v9.51,10.51 6.51,10.51 6.09,10.94 IC7.5
  Bottom 0.406: v24.31,14.51 24.31,13.71 21.11,10.51 v9.51,10.51
SCK  (via drill 0.4)
  Top 0.305: v22.21,95.21 IC1.17
  Bottom 0.305: ISP.3 25.53,98.53 v22.21,95.21
TXD  (via drill 0.4)
  Top 0.305: IC1.31 15.91,101.71 v15.61,101.41 | v8.31,87.41 6.39,87.41 IC2.4
  Bottom 0.305: v15.61,101.41 15.61,98.91 8.01,92.41 7.51,92.41 6.61,91.51 6.61,89.11 v8.31,87.41
TXD1
  Top 0.406: OK1.6 37.75,20.95 37.11,20.31 20.31,20.31 20.01,20.01 18.81,20.01 18.22,19.42 IC8.4
TXD_AL
  Top 0.406: OK1.3 37.75,17.68 36.81,17.81 22.31,17.81 21.21,16.71 21.21,15.61 20.31,14.71 10.11,14.71 8.94,13.54 IC7.1
XTAL1
  Top 0.406: Q1.3 10.68,96.86 | Q1.3 10.67,96.79 10.67,97.77 10.23,98.3 C5.2 | Q1.3 10.68,97.19 IC1.7
XTAL2
  Top 0.406: 9.28,93.85 12.57,93.85 13.61,94.89 IC1.8 | Q1.1 9.28,93.85 | 9.28,93.85 C4.2

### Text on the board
tPlace: seb@exse.net | Electron Buffer | 4CH LED-Controller | v2 | Power Injector | Data Injector
bStop: GND
_tNames: R | G | B | W | R13 | R12 | R10 | R14 | R11 | R2 | T2 | R3 | R4 | R5 | T1 | C2 | C3 | C5 | Q1 | R1 | ISP | C4 | IC1 | C8 | IC2 | C1 | R15 | L1 | C10 | R8 | D1 | IC3 | IC4 | C11 | R9 | R7 | C13 | C12 | R6 | C7 | C6 | C9 | +18 | D2 | GND | R24 | C17 | C22 | C25 | C15 | C16 | IC8 | IC6 | OK2 | IC7 | OK3 | OK1 | TX | R17 | C24 | R22 | RX | R16 | R19 | L2 | C21 | C20 | C19 | C14 | R18
_bNames: +5V
_tValues: SE14 | RJ45-8L-B | 100K | MEGA48/88/168-AU | 3,3µH | 8.2µH | 47µF 16V | 68k | 68k | 680pF | MBRS340 | 18k | 78L05SMD | 33k | 1µF | 1µF | 100nF | LT3972 | 4.7µF 50V | 150k | 4.7µF 50V | RJ45-8L-B | 4.7µF 50V | RJ45-8L-B | SE14 | RJ45-8L-B | RJ45-8L-B | SE14 | RJ45-8L-B | RJ45-8L-B | 78L05 | MAX487 | HCPL0601 | 4.7µF | RJ45-8L-B | FT232RL | USB-SMD-NS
